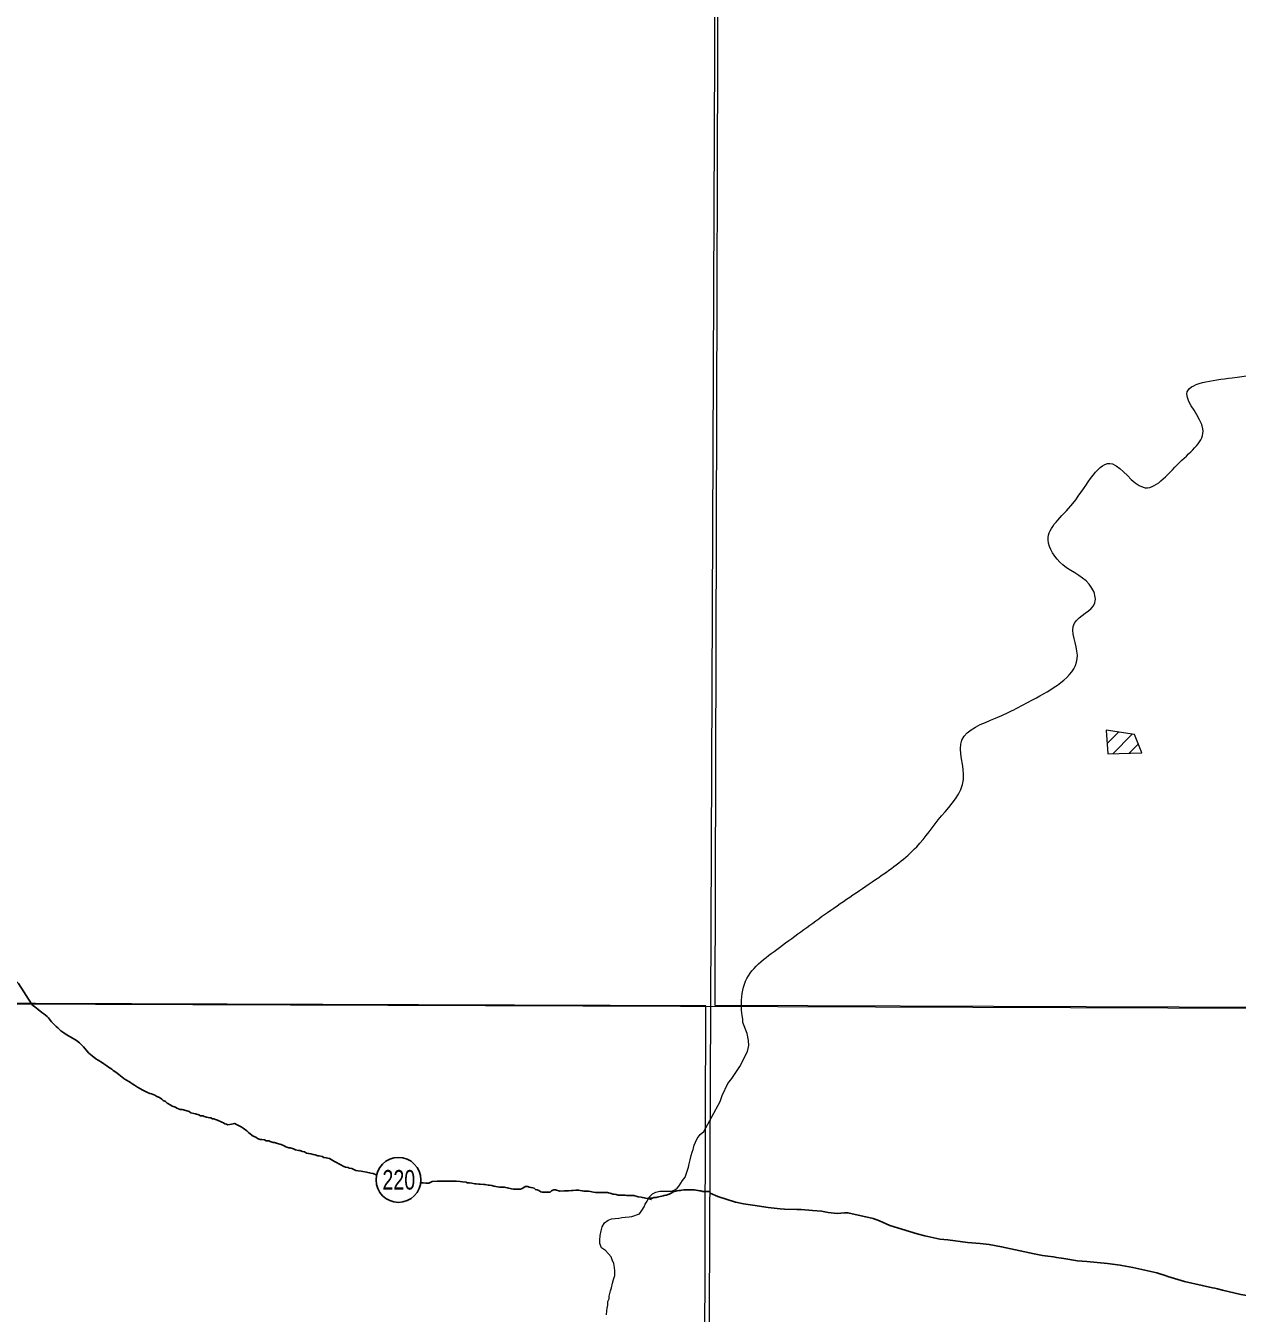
# Model space of a CAD drawing. Extents: x 553962 to 842807, y 8883888 to 9032388.
# Drawn here: x 594143 to 598478, y 8908832 to 8913437 of the extents above; entities that cross this region are included whole.
import ezdxf
from ezdxf.enums import TextEntityAlignment as Align

# ---------------------------------------------------------------- set-up
doc = ezdxf.new("R2010")
doc.units = 0
doc.header["$LTSCALE"] = 150
doc.layers.add('6', color=7, linetype='Continuous', lineweight=13)

msp = doc.modelspace()

# ---------------------------------------------------------------- linework, layer by layer
at = {"layer": '6'}
for p, q in [((598011.9, 8910870), (598052.8, 8910910.9)), ((598032.2, 8910833.7), (598101.8, 8910903.3)), ((598090.8, 8910835.7), (598123.8, 8910868.8)), ((574653.9, 8910009.3), (626625.7, 8909822.1))]:
    msp.add_line(p, q, dxfattribs=at)
at = {"layer": '6', "lineweight": 25}
msp.add_line((596590.3, 8909268.1), (596591.5, 8909261.3), dxfattribs=at)
at = {"layer": '6'}
for points in [[(596655.5, 8924715.8), (596593.3, 8909930.3), (596531.7, 8896026.7)], [(596627.8, 8909589.1), (596635.4, 8909611), (596655.3, 8909654), (596669.8, 8909672.5), (596698.4, 8909714.8), (596724.9, 8909769.1), (596729.8, 8909790.3), (596729.5, 8909807.5), (596724.5, 8909833.3), (596708.7, 8909872.6), (596708.4, 8909884.4), (596706.9, 8909897.8), (596703.8, 8909915.9)], [(596275.7, 8909174.6), (596288.2, 8909175.5), (596301.7, 8909176.9), (596311.7, 8909178.4), (596338.8, 8909188.3), (596347.8, 8909199.7), (596355.9, 8909212.7), (596359.4, 8909222.7), (596366.5, 8909233.7), (596373.6, 8909248.1), (596385.6, 8909259.1), (596397.7, 8909265.5), (596411.7, 8909268.9), (596453.7, 8909268.7), (596465.8, 8909273.5), (596474, 8909279.4), (596480.5, 8909287.6), (596487.5, 8909297.6), (596493.4, 8909307), (596502, 8909319.5), (596508.7, 8909337), (596514, 8909354.6), (596516.7, 8909367), (596520.3, 8909380.5), (596523.9, 8909397), (596527.4, 8909408), (596531, 8909417.9), (596535.1, 8909433.9), (596539.1, 8909443.9), (596545.7, 8909457.9), (596556.2, 8909471.9), (596569.8, 8909481.8), (596597.3, 8909535.3), (596627.8, 8909589.1)], [(596221, 8908826.6), (596222.1, 8908840.6), (596223.1, 8908851.1), (596225.2, 8908861.6), (596226.2, 8908874.6), (596230.3, 8908884.1), (596230.8, 8908893.6), (596235.4, 8908912.1), (596239, 8908923.6), (596243, 8908940.1), (596246.6, 8908953.6), (596250.7, 8908967.6), (596250.8, 8908984.6), (596249.8, 8908995.6), (596247.4, 8909010.6), (596240.9, 8909023.6), (596237.5, 8909034.2), (596228.5, 8909045.2), (596217.1, 8909056.8), (596203.1, 8909066.9), (596197.7, 8909081.4), (596197.7, 8909093.9), (596198.3, 8909109.9), (596201.9, 8909127.4), (596205.9, 8909140.9), (596214, 8909155.9), (596227.1, 8909164.8), (596238.6, 8909169.8), (596251.6, 8909171.7), (596265.1, 8909172.6), (596275.7, 8909174.6)]]:
    msp.add_lwpolyline(points, dxfattribs=at)
for points in [[(607600.8, 8920952.4), (596639.8, 8920989.8), (596608.8, 8909934.4), (607569.8, 8909894.9)], [(598009.1, 8910917.7), (598014.1, 8910833.1), (598136.5, 8910837.3), (598110.5, 8910902)], [(596575.8, 8909932.4), (585614.8, 8909969.8), (585583.8, 8898914.4), (596544.8, 8898874.9)]]:
    msp.add_lwpolyline(points, close=True, dxfattribs=at)
at = {"layer": '6', "lineweight": 25}
for points in [[(594065.1, 8910059.8), (594065.3, 8910056.9), (594071.5, 8910049.8), (594076.6, 8910045.4), (594082, 8910041.4), (594090.9, 8910033.6), (594094.4, 8910030.9), (594104.6, 8910026.1), (594117, 8910011.3), (594163.5, 8909939)], [(594163.5, 8909939), (594167.3, 8909934.5), (594175.7, 8909928), (594187.2, 8909918.9), (594200.6, 8909908.3), (594207.6, 8909903.2), (594220, 8909894.1), (594224.9, 8909888.6), (594235.3, 8909875), (594240.8, 8909869.4), (594251.7, 8909858.4), (594257.7, 8909853.3), (594268.6, 8909842.7), (594279.1, 8909834.7), (594284, 8909831.1), (594296.5, 8909824), (594304.5, 8909820), (594319.4, 8909811.8), (594324.9, 8909807.3), (594335.3, 8909799.2), (594340.3, 8909795.2), (594350.2, 8909785.6)], [(594350.2, 8909785.6), (594361.6, 8909770.5), (594369.1, 8909762.9), (594381, 8909752.9), (594393.9, 8909742.8), (594402.4, 8909737.7), (594417.8, 8909728.1), (594422.8, 8909724), (594433.7, 8909717), (594439.7, 8909712.9), (594451.2, 8909704.8), (594456.1, 8909700.8), (594465.6, 8909694.2), (594476, 8909686.1), (594482, 8909681.1), (594493.9, 8909672.5), (594500.9, 8909667.4), (594514.3, 8909659.8), (594518.8, 8909656.8), (594526.8, 8909651.2), (594532.2, 8909648.2), (594543.7, 8909641.1), (594553.7, 8909634.6), (594559.6, 8909631.5), (594571.6, 8909625.9), (594576.6, 8909622.9), (594587.5, 8909617.8), (594593, 8909616.8), (594605.5, 8909612.2), (594612.5, 8909607.1), (594622, 8909603.6), (594630.4, 8909598.5), (594635.4, 8909593.4), (594643.8, 8909589.4), (594649.3, 8909584.3), (594661.8, 8909576.2), (594667.2, 8909573.2), (594678.7, 8909569.6), (594684.2, 8909565.6), (594695.7, 8909561.5), (594702.7, 8909561), (594715.6, 8909557.9), (594727.6, 8909553.8), (594733.6, 8909549.7), (594745.1, 8909546.2), (594751.1, 8909546.1), (594763, 8909541.5), (594768.5, 8909538.5), (594777.5, 8909537.9), (594782, 8909536.4), (594790, 8909533.3), (594795.5, 8909532.8), (594801.5, 8909531.3), (594806, 8909530.7), (594811.5, 8909527.7), (594816.5, 8909527.2), (594822.4, 8909525.1), (594828.9, 8909523.1), (594833.9, 8909521), (594840.4, 8909518.5), (594844.9, 8909515.5), (594850.4, 8909513.4), (594855.8, 8909509.4), (594861.3, 8909508.8), (594865.8, 8909506.8), (594879.8, 8909508.2)], [(594879.8, 8909508.2), (594890.9, 8909511.2), (594897.3, 8909507.1), (594913.8, 8909499.5), (594920.8, 8909494.9), (594934.7, 8909484.8), (594940.7, 8909479.3), (594952.1, 8909468.7), (594957.1, 8909465.7), (594966.5, 8909462.1), (594972.5, 8909457.5), (594982.5, 8909454), (594987.5, 8909453.9), (594997, 8909452.4), (595003, 8909449.3), (595013.4, 8909448.8), (595017.9, 8909447.2), (595027.9, 8909443.2), (595033.4, 8909442.6), (595043.4, 8909439.5), (595052.4, 8909436.5), (595057.4, 8909435.4), (595068.3, 8909430.9), (595073.8, 8909427.8), (595084.3, 8909424.2), (595089.3, 8909424.2), (595101.8, 8909420.6), (595108.8, 8909417.1), (595119.7, 8909414), (595124.2, 8909414), (595133.2, 8909410.9), (595140.2, 8909409.4), (595148.2, 8909405.3), (595155.2, 8909404.2), (595163.2, 8909402.7), (595171.2, 8909400.1), (595179.1, 8909398.6), (595188.1, 8909395.5), (595193.1, 8909395), (595203.6, 8909393.4), (595210.1, 8909389.9), (595218.1, 8909388.8), (595223.6, 8909387.3), (595230.1, 8909386.2), (595235.5, 8909382.2), (595241.5, 8909379.2), (595248, 8909375.6), (595255, 8909372.1), (595262.9, 8909367), (595270.9, 8909362.9), (595278.9, 8909358.9), (595287.8, 8909355.3), (595296.3, 8909354.2), (595300.8, 8909350.7), (595310.3, 8909350.2), (595317.3, 8909346.6), (595324.8, 8909343.1), (595332.8, 8909342), (595343.3, 8909340.4), (595349.8, 8909338.9), (595362.2, 8909337.3), (595366.7, 8909335.8), (595373.2, 8909334.7), (595378.2, 8909333.2), (595386.7, 8909331.6), (595397.5, 8909327.7)], [(595557.4, 8909298.7), (595561.5, 8909298.4), (595565.6, 8909298.4), (595574.5, 8909297.8), (595579.1, 8909297.8), (595585.6, 8909297.8), (595597.6, 8909303.7)], [(595597.6, 8909303.7), (595615.6, 8909305.1), (595622.6, 8909305), (595627.6, 8909305), (595639.1, 8909304.9), (595644.1, 8909304.9), (595655.6, 8909304.8), (595662.1, 8909304.8), (595676.6, 8909304.7), (595683.6, 8909304.6), (595697.6, 8909303), (595705.6, 8909302), (595718.6, 8909300.9), (595723.1, 8909299.3), (595731.1, 8909298.3), (595739.6, 8909297.2), (595750.1, 8909295.7), (595754.6, 8909295.1), (595764.1, 8909294.6), (595769.1, 8909294), (595781.6, 8909293), (595787.1, 8909292.4), (595797.6, 8909290.8), (595802.6, 8909290.3), (595811.1, 8909289.3), (595817.6, 8909287.2), (595824.6, 8909285.7), (595831.1, 8909284.1), (595838.1, 8909283.6), (595844.6, 8909283.5), (595850.1, 8909283), (595856.1, 8909282.9), (595860.6, 8909281.9), (595866.1, 8909281.4), (595871, 8909280.3), (595876, 8909278.8), (595881.5, 8909277.8), (595888.5, 8909276.7), (595895, 8909276.2), (595900.5, 8909275.7), (595907.5, 8909275.6), (595913, 8909275.6), (595919.1, 8909278.5), (595925.6, 8909282.5), (595929.6, 8909285.5), (595933.6, 8909285.9), (595939.6, 8909285.9), (595944.6, 8909283.4), (595951.1, 8909281.8), (595957.1, 8909280.8), (595962.1, 8909279.2), (595966.5, 8909274.7), (595972.5, 8909274.2), (595978.5, 8909271.1), (595985.5, 8909266.1), (595990.5, 8909266), (595998.5, 8909265), (596002.5, 8909265), (596008, 8909264.9), (596012, 8909264.9), (596016, 8909264.9), (596020, 8909265.8), (596024, 8909269.8), (596028.6, 8909272.8), (596032.6, 8909273.8), (596038.6, 8909273.7), (596054.5, 8909269.1)], [(596054.5, 8909269.1), (596070.6, 8909270.5), (596075.6, 8909270.5), (596081.1, 8909270.4), (596085.1, 8909270.4), (596096.1, 8909270.8), (596101.6, 8909271.8), (596111.1, 8909272.2), (596117.6, 8909272.2), (596121.6, 8909272.2), (596127.1, 8909271.1), (596135.1, 8909269.6), (596139.6, 8909269.1), (596146.1, 8909269), (596152.1, 8909269), (596156.6, 8909268.4), (596163.6, 8909267.4), (596169.1, 8909266.4), (596174.6, 8909265.3), (596181.6, 8909264.8), (596187.6, 8909264.7), (596193.1, 8909264.2), (596200.1, 8909264.2), (596206.6, 8909264.1), (596212.1, 8909264.1), (596218.6, 8909264), (596224.1, 8909264), (596228.6, 8909263.5), (596233.1, 8909262.4), (596237.6, 8909260.9), (596244, 8909258.8), (596248.5, 8909258.3), (596255.5, 8909257.3), (596262.5, 8909255.2), (596268, 8909254.7), (596273.5, 8909254.7), (596279.5, 8909254.6), (596287.5, 8909254.6), (596292, 8909254), (596301.5, 8909254), (596306.5, 8909253.4), (596312.5, 8909253.4), (596318.5, 8909253.3), (596334, 8909249.2)], [(596334, 8909249.2), (596344.5, 8909247.2), (596349.5, 8909246.1), (596356, 8909245.6), (596381.5, 8909239.4)], [(596381.5, 8909239.4), (596369, 8909243.5), (596375, 8909243.5), (596379, 8909243.4), (596386, 8909244.4), (596390.5, 8909245.9), (596398.5, 8909246.8), (596402.5, 8909247.8), (596407.5, 8909248.3), (596413.6, 8909249.7), (596418.6, 8909250.7), (596423.6, 8909252.2), (596427.6, 8909253.1), (596431.6, 8909254.1), (596435.6, 8909255.1), (596441.6, 8909257), (596445.6, 8909258), (596449.7, 8909261), (596455.2, 8909263), (596459.7, 8909266.4), (596463.7, 8909267.4), (596469.2, 8909269.4), (596473.2, 8909270.4), (596479.2, 8909271.3), (596485.8, 8909271.8), (596490.8, 8909272.7), (596497.8, 8909274.2), (596501.8, 8909274.2), (596507.3, 8909274.1), (596511.3, 8909274.1), (596515.3, 8909274.1), (596519.3, 8909274.1), (596524.3, 8909274), (596528.3, 8909274), (596534.8, 8909273.9), (596541.3, 8909272.4), (596547.8, 8909271.4), (596553.3, 8909270.3), (596558.3, 8909269.8), (596564.3, 8909268.2), (596568.3, 8909268.2), (596574.3, 8909268.2), (596580.3, 8909268.1), (596585.8, 8909268.1), (596590.3, 8909268.1)], [(596591.5, 8909261.3), (596619.6, 8909249.8), (596682.6, 8909229.6), (596683.9, 8909229.3)], [(596683.9, 8909229.3), (596711.5, 8909223.7), (596744.5, 8909219.2), (596799.3, 8909210.1), (596842.1, 8909206.1)], [(596842.1, 8909206.1), (596858.3, 8909204.6), (596902.4, 8909203.4)], [(596902.4, 8909203.4), (596917, 8909203.1), (596957.6, 8909199.9)], [(596957.6, 8909199.9), (596990.5, 8909197.3), (597014.2, 8909192.9), (597045.7, 8909189.7), (597072.2, 8909191.1)], [(597072.2, 8909191.1), (597084.7, 8909191.8), (597174.5, 8909170.9), (597197.8, 8909163.1), (597234.6, 8909146.1), (597332.2, 8909115.9), (597359.4, 8909109.1), (597359.4, 8909109.1)], [(597359.4, 8909109.1), (597413.5, 8909097.8), (597441.7, 8909094.5)], [(597441.7, 8909094.5), (597513, 8909085.9), (597557.5, 8909082.1), (597590.5, 8909077.7), (597634.7, 8909070.3), (597750.9, 8909045), (597780.8, 8909039.3), (597800, 8909036.6)], [(597800, 8909036.6), (597820.6, 8909033.7), (597826.4, 8909032.4)], [(597826.4, 8909032.4), (597831.3, 8909031.2), (597848.5, 8909029.3), (597857.5, 8909027.9)], [(597857.5, 8909027.9), (597905.8, 8909020.3), (597940, 8909016.9)], [(597940, 8909016.9), (598013.1, 8909009.7), (598058.4, 8909004.1), (598065, 8909003)], [(598065, 8909003), (598103.6, 8908996.2), (598190.4, 8908976.9), (598223.4, 8908965.7), (598229, 8908963.9)], [(598229, 8908963.9), (598288.9, 8908945.4), (598352.3, 8908932.1), (598389.3, 8908922.7), (598397.9, 8908921.9), (598406.4, 8908919.8), (598424.8, 8908915.4)], [(598424.8, 8908915.4), (598490.2, 8908899.6), (598588.7, 8908882.5), (598615.2, 8908875.7), (598623.3, 8908875.6)]]:
    msp.add_lwpolyline(points, dxfattribs=at)
msp.add_circle((595476.7, 8909309.2), 80.3, dxfattribs=at)
at = {"layer": '6'}
msp.add_spline([(596703.8, 8909915.9), (596714.2, 8910009.9), (596839.6, 8910140.6), (597012.1, 8910266), (597195, 8910391.4), (597330.8, 8910501.1), (597419.6, 8910610.8), (597498, 8910741.4), (597492.8, 8910882.5), (597613, 8910960.9), (597759.2, 8911034), (597905.6, 8911185.6), (597895.1, 8911300.5), (597968.2, 8911373.7), (597957.8, 8911425.9), (597853.3, 8911509.5), (597801.1, 8911598.3), (597889.9, 8911729), (598031, 8911870), (598140.7, 8911786.4), (598271.3, 8911875.3), (598354.9, 8911995.4), (598297.4, 8912120.8), (598459.4, 8912178.3), (598694.5, 8912204.4), (598882.6, 8912209.7), (599112.5, 8912314.2), (599201.4, 8912340.3), (599285, 8912455.2), (599384.2, 8912502.3), (599426, 8912612.4), (599520.1, 8912769.3), (599645.5, 8912873.8), (599650.7, 8912967.9), (599603.7, 8913082.9), (599520.1, 8913229.3), (599285, 8913417.5)], degree=3, dxfattribs=at)

# ---------------------------------------------------------------- texts
at = {"layer": '6', "width": 0.75}
msp.add_text('220', height=70, dxfattribs=at).set_placement((595478, 8909274.6), align=Align.CENTER)

doc.saveas('drawing.dxf')
